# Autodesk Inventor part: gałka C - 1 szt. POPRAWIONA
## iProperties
Created: 2024-06
Part Number: gałka C - 1 szt. POPRAWIONA
Document SubType Name: Modeling
Designer: Tomasz Łysek
Density: 1 g/cm^3
Author: Tomasz Łysek
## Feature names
1. Wyciągnięcie proste1 [Extrusion]
2. Wyciągnięcie proste2 [Extrusion]
3. Wyciągnięcie proste5 [Extrusion]
4. Faza1 [Chamfer]
5. Wyciągnięcie proste6 [Extrusion]
